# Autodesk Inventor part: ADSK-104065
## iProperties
Shininess: 0.0
Created: 2000-04
Part Number: ADSK-104065
Document SubType Name: Modeling
Stock Number: ADSK-104065
Density: 1 g/cm^3
Density: 0.0
Volumn: 0.0
Area: 0.0
PropertySet Name: Model Information
Control State: 0
Checked Out: False
Master: False
Author: gao
